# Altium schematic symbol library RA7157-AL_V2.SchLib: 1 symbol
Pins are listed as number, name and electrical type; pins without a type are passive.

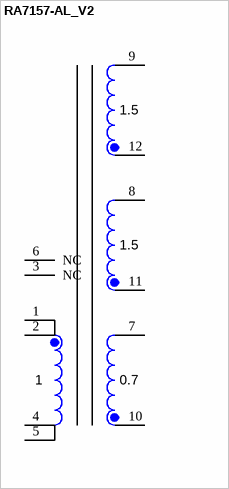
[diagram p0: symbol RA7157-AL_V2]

## RA7157-AL_V2
designator T?, comment RA7157-AL
1:1.5:1.5:0.7 Turns Ratio Transformer; Manufacturer: Coilcraft; SymbolCreator: a0412036; U/M: EA; Value: 50uH
footprint RA7157-AL (COILCRAFT RA7157-AL CUSTOM TRANSFORMER)
pins: 1, 2, 3 NC, 4, 5, 6 NC, 7, 8, 9, 10, 11, 12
